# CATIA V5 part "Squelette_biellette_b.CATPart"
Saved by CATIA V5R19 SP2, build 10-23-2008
Part number: squelette_biellette_b
Bounding box of the stored display mesh (mm): x 40 to 55, y -294 to -294, z -144 to -48
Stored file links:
  G:\EU_thinkMotion\CFAO_2010\MMS_groupe3\MMS_groupe3\pmayet\pmayet_assemblage_animation\pmayet_assemblage_animation\Squelette_biellette_b.CATPart
  G:\EU_thinkMotion\CFAO_2010\MMS_groupe3\MMS_groupe3\pmayet\pmayet_assemblage_animation\pmayet_assemblage_animation\pmayet_assemblage_animation.CATProduct
  G:\EU_thinkMotion\CFAO_2010\MMS_groupe3\MMS_groupe3\pmayet\pmayet_assemblage_animation\pmayet_assemblage_animation\Barre_bas.CATPart
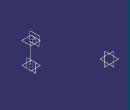
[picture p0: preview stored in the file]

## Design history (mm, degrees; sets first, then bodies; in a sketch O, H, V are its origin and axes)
Set1
  Point1: linked copy from another document
  Point2: linked copy from another document
  Plane1: linked copy from another document
  Point3: linked copy from another document
Set2
  Line1: type PtPt, FirstPoint Point1, SecondPoint Point3
  Plane2: type OffsetPt, RefPlane Plane1, RefPoint Point1
  Plane3: type Normal, Curve Line1, RefPoint Point1
  Plane4: type Normal, Curve Line1, RefPoint Point3
Body1 (main body)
